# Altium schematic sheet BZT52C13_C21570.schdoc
size 127 x 101 mm
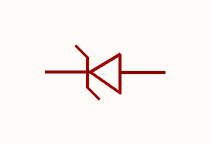
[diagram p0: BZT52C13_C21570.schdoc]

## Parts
ZD?  bzt52c13_c21570  [SOD-123_L2.8-W1.8-LS3.7-RD]  (value not drawn)

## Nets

Not connected (* = marked no-connect by the designer): ZD? 1(K) 2(A)

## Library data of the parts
ZD? = bzt52c13_c21570: 二极管配置:1个独立式;稳压值(标称值):13V;稳压值(范围):12.4V~14.1V;耗散功率(Pd):500mW;; Manufacturer: CJ(江苏长电/长晶); AddInBom: yes; ModelId: 7884390a25fb4c08947731ebfba7e3f8; ModelTransform: 144.8816,62.992,0,0,0,0,0,0,0; Diode Configuration: 1个独立式; Zener Voltage(Nom): 13V; Reverse Leakage Current (Ir): 100nA@8V; Pd - Power Dissipation: 500mW; Impedance(Zzt): 30Ω; Impedance(Zzk): 170Ω; Operating Junction Temperature Range: -55℃~+150℃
